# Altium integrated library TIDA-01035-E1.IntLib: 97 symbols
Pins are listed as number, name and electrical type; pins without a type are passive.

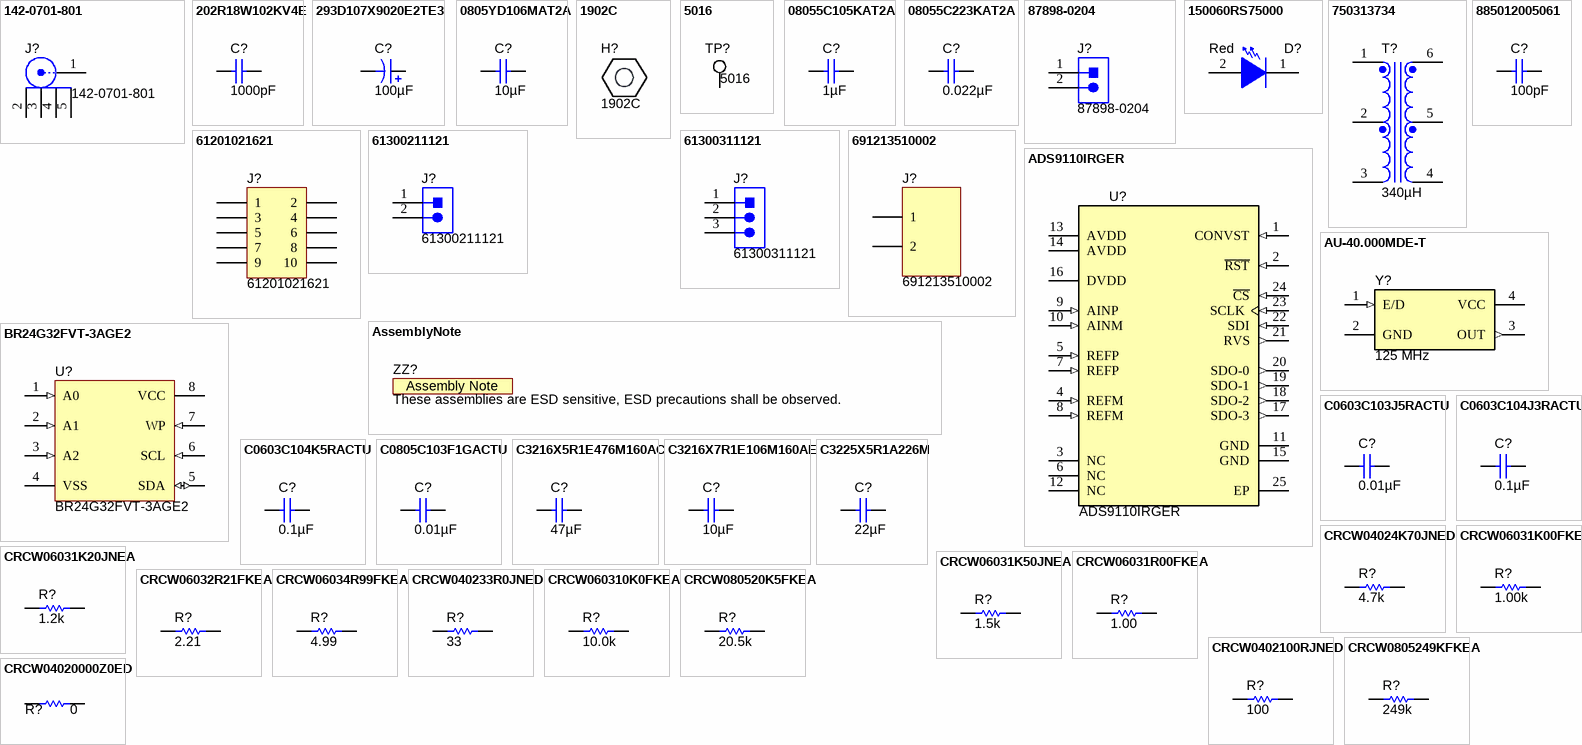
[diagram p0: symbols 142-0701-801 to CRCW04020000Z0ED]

## 142-0701-801
designator J?
Connector, End launch SMA, 50 ohm, SMT; Manufacturer: Johnson; SymbolCreator: X0208326; U/M: EA
footprint JOHNSON_142-0701-801
footprint JOHNSON_142-0701-801_NoVias
pins: 1, 2, 3, 4, 5

## 202R18W102KV4E
designator C?  ValueDisplayed: 1000pF  (hidden comment: 202R18W102KV4E)
CAP, CERM, 1000 pF, 2000 V, +/- 10%, X7R, 1206_190; Manufacturer: Johanson Technology; Polarized: N; CompType: Capacitor; Value: 1000pF; U/M: EA; Cap_F: 0.000000001; Tolerance_%: 10; Value1: Unknown; VDC_V: 2000; Value2: 2000V; TaMin_C: -55; TaMax_C: 125; Cap_Case: 1206; AEC Category: Q200
signal-integrity model Cap
simulation model Cap
footprint 1206_190
footprint 1206_190M
footprint 1206_190L
pins: 1, 2

## 293D107X9020E2TE3
designator C?  ValueDisplayed: 100µF  (hidden comment: 293D107X9020E2TE3)
CAP, TA, 100 µF, 20 V, +/- 10%, 0.5 ohm, SMD; Manufacturer: Vishay-Sprague; Polarized: Y; CompType: Capacitor; Value: 100uF; U/M: EA; Cap_F: 0.0001; Tolerance_%: 10; Value1: 0.5 ohm; VDC_V: 20; Value2: 20V; ESR_ohm: 0.5; IRMS_A: 0.57; TaMin_C: -55; TaMax_C: 125; Cap_Case: E; AEC Category: Q200
signal-integrity model Cap
simulation model Cap
footprint 7343-43
pins: 1 +, 2 -

## 0805YD106MAT2A
designator C?  ValueDisplayed: 10µF  (hidden comment: 0805YD106MAT2A)
CAP, CERM, 10uF, 16V, +/-20%, X5R, 0805; Manufacturer: AVX; Polarized: N; CompType: Capacitor; U/M: EA; Cap_F: 0.00001; Tolerance_%: 20; Value1: Unknown; VDC_V: 16; TaMin_C: -55; TaMax_C: 85; Cap_Case: 0805
signal-integrity model Cap
simulation model Cap
footprint 0805_HV
footprint 0805
footprint 0805M
footprint 0805L
pins: 1, 2

## 1902C
designator H?
Standoff, Hex, 0.5"L #4-40 Nylon; Manufacturer: Keystone; CompType: Hardware
footprint Keystone_1902C

## 5016
designator TP?
Test Point, Compact, SMT; Manufacturer: Keystone; CompType: Test Point Loop; U/M: EA
footprint Testpoint_Keystone_Compact
pins: 1

## 08055C105KAT2A
designator C?  ValueDisplayed: 1µF  (hidden comment: 08055C105KAT2A)
CAP, CERM, 1uF, 50V, +/-10%, X7R, 0805; Manufacturer: AVX; Polarized: N; CompType: Capacitor; U/M: EA; Cap_F: 0.000001; Tolerance_%: 10; Value1: Unknown; VDC_V: 50; TaMin_C: -55; TaMax_C: 125; Cap_Case: 0805
signal-integrity model Cap
simulation model Cap
footprint 0805_HV
footprint 0805
footprint 0805M
footprint 0805L
pins: 1, 2

## 08055C223KAT2A
designator C?  ValueDisplayed: 0.022µF  (hidden comment: 08055C223KAT2A)
CAP, CERM, 0.022uF, 50V, +/-10%, X7R, 0805; Manufacturer: AVX; Polarized: N; CompType: Capacitor; U/M: EA; Cap_F: 0.000000022; Tolerance_%: 10; ESR_Ohm: 0.052; Value1: 0.052 ohm; VDC_V: 50; TaMin_C: -55; TaMax_C: 125; Cap_Case: 0805
signal-integrity model Cap
simulation model Cap
footprint 0805_HV
footprint 0805
footprint 0805M
footprint 0805L
pins: 1, 2

## 87898-0204
designator J?
Header, 2.54 mm, 2x1, Gold, R/A, SMT; Manufacturer: Molex; SymbolCreator: a0412235; U/M: EA
footprint Molex_87898-0204
pins: 1, 2
1 alternate drawing of the same symbol

## 150060RS75000
designator D?  value Red  (hidden comment: 150060RS75000)
LED, Red, SMD; Manufacturer: Wurth Elektronik; Type: AlInGaP; Vf_V: 2; Value2: 2V; Io_A: 0.03; Vr_V: 5; Tjmax_C: 85; Power_TotalModule: 0.072; Value1: 0.072W; Angle: 140; U/M: EA
signal-integrity model Diode
footprint WL-SMCW_RED
pins: 1 K, 2 A

## 750313734
designator T?  ValueDisplayed: 340µH  (hidden comment: 750313734)
Transformer, 340 uH, TH; Manufacturer: Wurth Elektronik; SymbolCreator: Altium; Value: 340uH; Lp: 340; DCR_ohm: 0.419
footprint Wurth_750313638
pins: 1, 2, 3, 4, 5, 6

## 61201021621
designator J?
WR-BHD 2.54mm Male Box Header; Manufacturer: Wurth Elektronik; ComponentLink1 Description: Manufacturer; ComponentLink2 Description: Datasheet; NoPins: 10
footprint 61201021621 (10 pins, straight, gold plating)
pins: 1, 2, 3, 4, 5, 6, 7, 8, 9, 10

## 61300211121
designator J?
Header, 2.54 mm, 2x1, Gold, TH; Manufacturer: Wurth Elektronik eiSos; SymbolCreator: a0412235; U/M: EA
footprint WURTH_61300211121
pins: 1, 2
1 alternate drawing of the same symbol

## 61300311121
designator J?
Header, 2.54 mm, 3x1, Gold, TH; Manufacturer: Wurth Elektronik eiSos; SymbolCreator: a0799628; U/M: EA
footprint WURTH_61300311121
pins: 1, 2, 3
2 alternate drawings of the same symbol

## 691213510002
designator J?
Horizontal Cable Entry with Rising Cage Clamp, Serie 2135 - 5.08 mm; Manufacturer: Wurth Elektronik; ComponentLink1 Description: Manufacturer; ComponentLink2 Description: Datasheet; NoPins: 2
footprint 691213510002 (Serie 2135 - 5.08 mm _ 2 pins)
pins: 1, 2

## 885012005061
designator C?  ValueDisplayed: 100pF  (hidden comment: 885012005061)
CAP, CERM, 100 pF, 50 V, +/- 5%, C0G/NP0, 0402; Manufacturer: Wurth Elektronik; Polarized: N; CompType: Capacitor; Value: 100pF; U/M: EA; Cap_F: 0.0000000001; Tolerance_%: 5; Value1: Unknown; VDC_V: 50; Value2: 50V; TaMin_C: -55; TaMax_C: 125; Cap_Case: 0402; AEC Category: Q200
signal-integrity model Cap
simulation model Cap
footprint 0402
footprint 0402M
footprint 0402L
footprint 0402S
pins: 1, 2

## ADS9110IRGER
designator U?
18-Bit, 2-MSPS, 20-mW, SAR ADC with Enhanced Serial Interface, RGE0024H; Alternate PartNumber: ADS9110IRGET; Manufacturer: Texas Instruments; SymbolCreator: Altium; CompType: IC; U/M: EA
footprint RGE0024H
footprint RGE0024H_NV
pins: 1 CONVST (in), 2 ~{RST} (in), 3 NC, 4 REFM (in), 5 REFP (in), 6 NC, 7 REFP (in), 8 REFM (in), 9 AINP (in), 10 AINM (in), 11 GND (power), 12 NC (power), 13 AVDD (power), 14 AVDD (power), 15 GND (power), 16 DVDD (power), 17 SDO-3 (out), 18 SDO-2 (out), 19 SDO-1 (out), 20 SDO-0 (out), 21 RVS (out), 22 SDI (in), 23 SCLK (in), 24 ~{CS} (in), 25 EP (power)

## AssemblyNote
designator ZZ?, comment These assemblies are ESD sensitive, ESD precautions shall be observed.  (no BOM)
SymbolCreator: codlsc; CompType: AssemblyNote
footprint AssemblyNote

## AU-40.000MDE-T
designator Y?, comment Frequency: 125 MHz  (hidden comment: ASTMLPE-125.000MHZ-LJ-E-T)
OSC, 125 MHz, 3.3V, SMD; Manufacturer: ABRACON; SymbolCreator: a0411947; CompType: Oscillator; U/M: EA; TaMin_C: -40; TaMax_C: 85; Frequency Stability: ±50ppm
footprint TXC_AU
pins: 1 E/D (in), 2 GND (power), 3 OUT (out), 4 VCC (power)

## BR24G32FVT-3AGE2
designator U?
I2C BUS EEPROM (2-Wire), TSSOP-B8; Manufacturer: Rohm; SymbolCreator: a0411947
footprint TSOP65P640X120-8N
footprint TSOP65P640X120-8M
footprint TSOP65P640X120-8L
pins: 1 A0 (in), 2 A1 (in), 3 A2 (in), 4 VSS (power), 5 SDA (io), 6 SCL (in), 7 WP (in), 8 VCC (power)

## C0603C103J5RACTU
designator C?  ValueDisplayed: 0.01µF  (hidden comment: C0603C103J5RACTU)
CAP, CERM, 0.01uF, 50V, +/-5%, X7R, 0603; Manufacturer: Kemet; Polarized: N; CompType: Capacitor; U/M: EA; Cap_F: 0.00000001; Tolerance_%: 5; Value1: Unknown; VDC_V: 50; TaMin_C: -55; TaMax_C: 125; Cap_Case: 0603
signal-integrity model Cap
simulation model Cap
footprint 0603
footprint 0603M
footprint 0603L
footprint 0603_HV
pins: 1, 2

## C0603C104J3RACTU
designator C?  ValueDisplayed: 0.1µF  (hidden comment: C0603C104J3RACTU)
CAP, CERM, 0.1 µF, 25 V, +/- 5%, X7R, 0603; Manufacturer: Kemet; Polarized: N; CompType: Capacitor; Value: 0.1uF; U/M: EA; Cap_F: 0.0000001; Tolerance_%: 5; Value1: Unknown; VDC_V: 25; Value2: 25V; TaMin_C: -55; TaMax_C: 125; Cap_Case: 0603
signal-integrity model Cap
simulation model Cap
footprint 0603
footprint 0603M
footprint 0603L
footprint 0603_HV
footprint 0603S
pins: 1, 2

## C0603C104K5RACTU
designator C?  ValueDisplayed: 0.1µF  (hidden comment: C0603C104K5RACTU)
CAP, CERM, 0.1uF, 50V, +/-10%, X7R, 0603; Manufacturer: Kemet; Polarized: N; CompType: Capacitor; U/M: EA; Cap_F: 0.0000001; Tolerance_%: 10; Value1: Unknown; VDC_V: 50; TaMin_C: -55; TaMax_C: 125; Cap_Case: 0603
signal-integrity model Cap
simulation model Cap
footprint 0603
footprint 0603M
footprint 0603L
footprint 0603_HV
pins: 1, 2

## C0805C103F1GACTU
designator C?  ValueDisplayed: 0.01µF  (hidden comment: C0805C103F1GACTU)
CAP, CERM, 0.01 µF, 100 V, +/- 1%, C0G/NP0, 0805; Manufacturer: Kemet; Polarized: N; CompType: Capacitor; Value: 0.01uF; U/M: EA; Cap_F: 0.00000001; Tolerance_%: 1; Value1: Unknown; VDC_V: 100; Value2: 100V; TaMin_C: -55; TaMax_C: 125; Cap_Case: 0805; AEC Category: Q200
signal-integrity model Cap
simulation model Cap
footprint 0805_HV
footprint 0805_HV1
footprint 0805
footprint 0805M
footprint 0805L
pins: 1, 2

## C3216X5R1E476M160AC
designator C?  ValueDisplayed: 47µF  (hidden comment: C3216X5R1E476M160AC)
CAP, CERM, 47 µF, 25 V, +/- 20%, X5R, 1206_190; Manufacturer: TDK; Polarized: N; CompType: Capacitor; Value: 47uF; U/M: EA; Cap_F: 0.000047; Tolerance_%: 20; Value1: Unknown; VDC_V: 25; Value2: 25V; TaMin_C: -55; TaMax_C: 85; Cap_Case: 1206; AEC Category: Q200
signal-integrity model Cap
simulation model Cap
footprint 1206_190
footprint 1206_190M
footprint 1206_190L
pins: 1, 2

## C3216X7R1E106M160AE
designator C?  ValueDisplayed: 10µF  (hidden comment: C3216X7R1E106M160AE)
CAP, CERM, 10 µF, 25 V, +/- 20%, X7R, 1206_190; Manufacturer: TDK; Polarized: N; CompType: Capacitor; Value: 10uF; U/M: EA; Cap_F: 0.00001; Tolerance_%: 20; Value1: Unknown; VDC_V: 25; Value2: 25V; TaMin_C: -55; TaMax_C: 125; Cap_Case: 1206; AEC Category: Q200
signal-integrity model Cap
simulation model Cap
footprint 1206_190
footprint 1206_190M
footprint 1206_190L
pins: 1, 2

## C3225X5R1A226M
designator C?  ValueDisplayed: 22µF  (hidden comment: C3225X5R1A226M)
CAP, CERM, 22uF, 10V, +/-20%, X5R, 1210; Manufacturer: TDK; Polarized: N; CompType: Capacitor; U/M: EA; Cap_F: 0.000022; Tolerance_%: 20; ESR_Ohm: 0.002; Value1: 0.002 ohm; VDC_V: 10; IRMS_A: 3.2; TaMin_C: -55; TaMax_C: 85; Cap_Case: 1210
signal-integrity model Cap
simulation model Cap
footprint 1210 (1210 from SM-752 data)
footprint 1210M
footprint 1210L
pins: 1, 2

## CRCW04024K70JNED
designator R?  ValueDisplayed: 4.7k  (hidden comment: CRCW04024K70JNED)
RES, 4.7 k, 5%, 0.063 W, 0402; Manufacturer: Vishay-Dale; CompType: Resistor; Value: 4.7k; Res_ohm: 4700; Value_Code: 4k70; Tolerance_%: 5; Power_W: 0.063; Value2: 0.063W; VDC_V: 50; TempCo: 200 ppm/C; EIA_Code: E24; U/M: EA; AEC Category: Q200
signal-integrity model Resistor
simulation model Resistor
footprint 0402
footprint 0402M
footprint 0402L
footprint 0402S
pins: 1, 2

## CRCW06031K00FKEA
designator R?  ValueDisplayed: 1.00k  (hidden comment: CRCW06031K00FKEA)
RES, 1.00 k, 1%, 0.1 W, 0603; Manufacturer: Vishay-Dale; CompType: Resistor; Value: 1.00k; Res_ohm: 1000; Value_Code: 1k00; Tolerance_%: 1; Power_W: 0.1; Value2: 0.1W; VDC_V: 75; TempCo: 100 ppm/C; EIA_Code: E96; U/M: EA; AEC Category: Q200
signal-integrity model Resistor
simulation model Resistor
footprint 0603
footprint 0603M
footprint 0603L
footprint 0603_HV
footprint 0603S
pins: 1, 2

## CRCW06031K20JNEA
designator R?  ValueDisplayed: 1.2k  (hidden comment: CRCW06031K20JNEA)
RES, 1.2 k, 5%, 0.1 W, 0603; Manufacturer: Vishay-Dale; CompType: Resistor; Value: 1.2k; Res_ohm: 1200; Value_Code: 1k20; Tolerance_%: 5; Power_W: 0.1; Value2: 0.1W; VDC_V: 75; TempCo: 200 ppm/C; EIA_Code: E24; U/M: EA; AEC Category: Q200
signal-integrity model Resistor
simulation model Resistor
footprint 0603
footprint 0603M
footprint 0603L
footprint 0603_HV
footprint 0603S
pins: 1, 2

## CRCW06031K50JNEA
designator R?  ValueDisplayed: 1.5k  (hidden comment: CRCW06031K50JNEA)
RES, 1.5 k, 5%, 0.1 W, 0603; Manufacturer: Vishay-Dale; CompType: Resistor; Value: 1.5k; Res_ohm: 1500; Value_Code: 1k50; Tolerance_%: 5; Power_W: 0.1; Value2: 0.1W; VDC_V: 75; TempCo: 200 ppm/C; EIA_Code: E24; U/M: EA; AEC Category: Q200
signal-integrity model Resistor
simulation model Resistor
footprint 0603
footprint 0603M
footprint 0603L
footprint 0603_HV
footprint 0603S
pins: 1, 2

## CRCW06031R00FKEA
designator R?  ValueDisplayed: 1.00  (hidden comment: CRCW06031R00FKEA)
RES, 1.00, 1%, 0.1 W, 0603; Manufacturer: Vishay-Dale; CompType: Resistor; Value: 1.00; Res_ohm: 1; Value_Code: 1R00; Power_W: 0.1; Value2: 0.1W; VDC_V: 75; TempCo: 100 ppm/C; EIA_Code: E96; U/M: EA; AEC Category: Q200
signal-integrity model Resistor
simulation model Resistor
footprint 0603
footprint 0603M
footprint 0603L
footprint 0603_HV
footprint 0603S
pins: 1, 2

## CRCW06032R21FKEA
designator R?  ValueDisplayed: 2.21  (hidden comment: CRCW06032R21FKEA)
RES, 2.21, 1%, 0.1 W, 0603; Manufacturer: Vishay-Dale; CompType: Resistor; Value: 2.21; Value_Code: 2R21; Tolerance_%: 1; Power_W: 0.1; Value2: 0.1W; VDC_V: 75; TempCo: 100 ppm/C; EIA_Code: E96; U/M: EA
signal-integrity model Resistor
simulation model Resistor
footprint 0603
footprint 0603M
footprint 0603L
footprint 0603_HV
footprint 0603S
pins: 1, 2

## CRCW06034R99FKEA
designator R?  ValueDisplayed: 4.99  (hidden comment: CRCW06034R99FKEA)
RES, 4.99, 1%, 0.1 W, 0603; Manufacturer: Vishay-Dale; CompType: Resistor; Value: 4.99; Value_Code: 4R99; Tolerance_%: 1; Power_W: 0.1; Value2: 0.1W; VDC_V: 75; TempCo: 100 ppm/C; EIA_Code: E96; U/M: EA; AEC Category: Q200
signal-integrity model Resistor
simulation model Resistor
footprint 0603
footprint 0603M
footprint 0603L
footprint 0603_HV
footprint 0603S
pins: 1, 2

## CRCW040233R0JNED
designator R?  ValueDisplayed: 33  (hidden comment: CRCW040233R0JNED)
RES, 33, 5%, 0.063 W, 0402; Manufacturer: Vishay-Dale; CompType: Resistor; Value: 33; Value_Code: 33R0; Tolerance_%: 5; Power_W: 0.063; Value2: 0.063W; VDC_V: 50; TempCo: 200 ppm/C; EIA_Code: E24; U/M: EA; AEC Category: Q200
signal-integrity model Resistor
simulation model Resistor
footprint 0402
footprint 0402M
footprint 0402L
footprint 0402S
pins: 1, 2

## CRCW060310K0FKEA
designator R?  ValueDisplayed: 10.0k  (hidden comment: CRCW060310K0FKEA)
RES, 10.0 k, 1%, 0.1 W, 0603; Manufacturer: Vishay-Dale; CompType: Resistor; Value: 10.0k; Res_ohm: 10000; Value_Code: 10k0; Tolerance_%: 1; Power_W: 0.1; Value2: 0.1W; VDC_V: 75; TempCo: 100 ppm/C; EIA_Code: E96; U/M: EA
signal-integrity model Resistor
simulation model Resistor
footprint 0603
footprint 0603M
footprint 0603L
footprint 0603_HV
footprint 0603S
pins: 1, 2

## CRCW080520K5FKEA
designator R?  ValueDisplayed: 20.5k  (hidden comment: CRCW080520K5FKEA)
RES, 20.5 k, 1%, 0.125 W, 0805; Manufacturer: Vishay-Dale; CompType: Resistor; Value: 20.5k; Res_ohm: 20500; Value_Code: 20k5; Tolerance_%: 1; Power_W: 0.125; Value2: 0.125W; VDC_V: 150; TempCo: 100 ppm/C; EIA_Code: E96; U/M: EA; AEC Category: Q200
signal-integrity model Resistor
simulation model Resistor
footprint 0805_HV
footprint 0805_HV1
footprint 0805
footprint 0805M
pins: 1, 2

## CRCW0402100RJNED
designator R?  ValueDisplayed: 100  (hidden comment: CRCW0402100RJNED)
RES, 100, 5%, 0.063 W, 0402; Manufacturer: Vishay-Dale; CompType: Resistor; Value: 100; Value_Code: 100R; Tolerance_%: 5; Power_W: 0.063; Value2: 0.063W; VDC_V: 50; TempCo: 200 ppm/C; EIA_Code: E24; U/M: EA; AEC Category: Q200
signal-integrity model Resistor
simulation model Resistor
footprint 0402
footprint 0402M
footprint 0402L
footprint 0402S
pins: 1, 2

## CRCW0805249KFKEA
designator R?  value 249k  (hidden comment: CRCW0805249KFKEA)
RES, 249k ohm, 1%, 0.125W, 0805; Manufacturer: Vishay-Dale; CompType: Resistor; Res_ohm: 249000; Tolerance_%: 1; Power_W: 0.125; VDC_V: 150; TempCo: 100 ppm/C; EIA_Code: E96; U/M: EA
signal-integrity model Resistor
simulation model Resistor
footprint 0805_HV
footprint 0805
footprint 0805M
footprint 0805L
pins: 1, 2

## CRCW04020000Z0ED
designator R?  ValueDisplayed: 0  (hidden comment: CRCW04020000Z0ED)
RES, 0, 5%, 0.063 W, 0402; Manufacturer: Vishay-Dale; CompType: Resistor; Value: 0; Value_Code: 0000; Tolerance_%: 5; Power_W: 0.063; Value2: 0.063W; VDC_V: 50; TempCo: 200 ppm/C; EIA_Code: E24; U/M: EA; AEC Category: Q200
signal-integrity model Resistor
simulation model Resistor
footprint 0402
footprint 0402M
footprint 0402L
footprint 0402S
pins: 1, 2

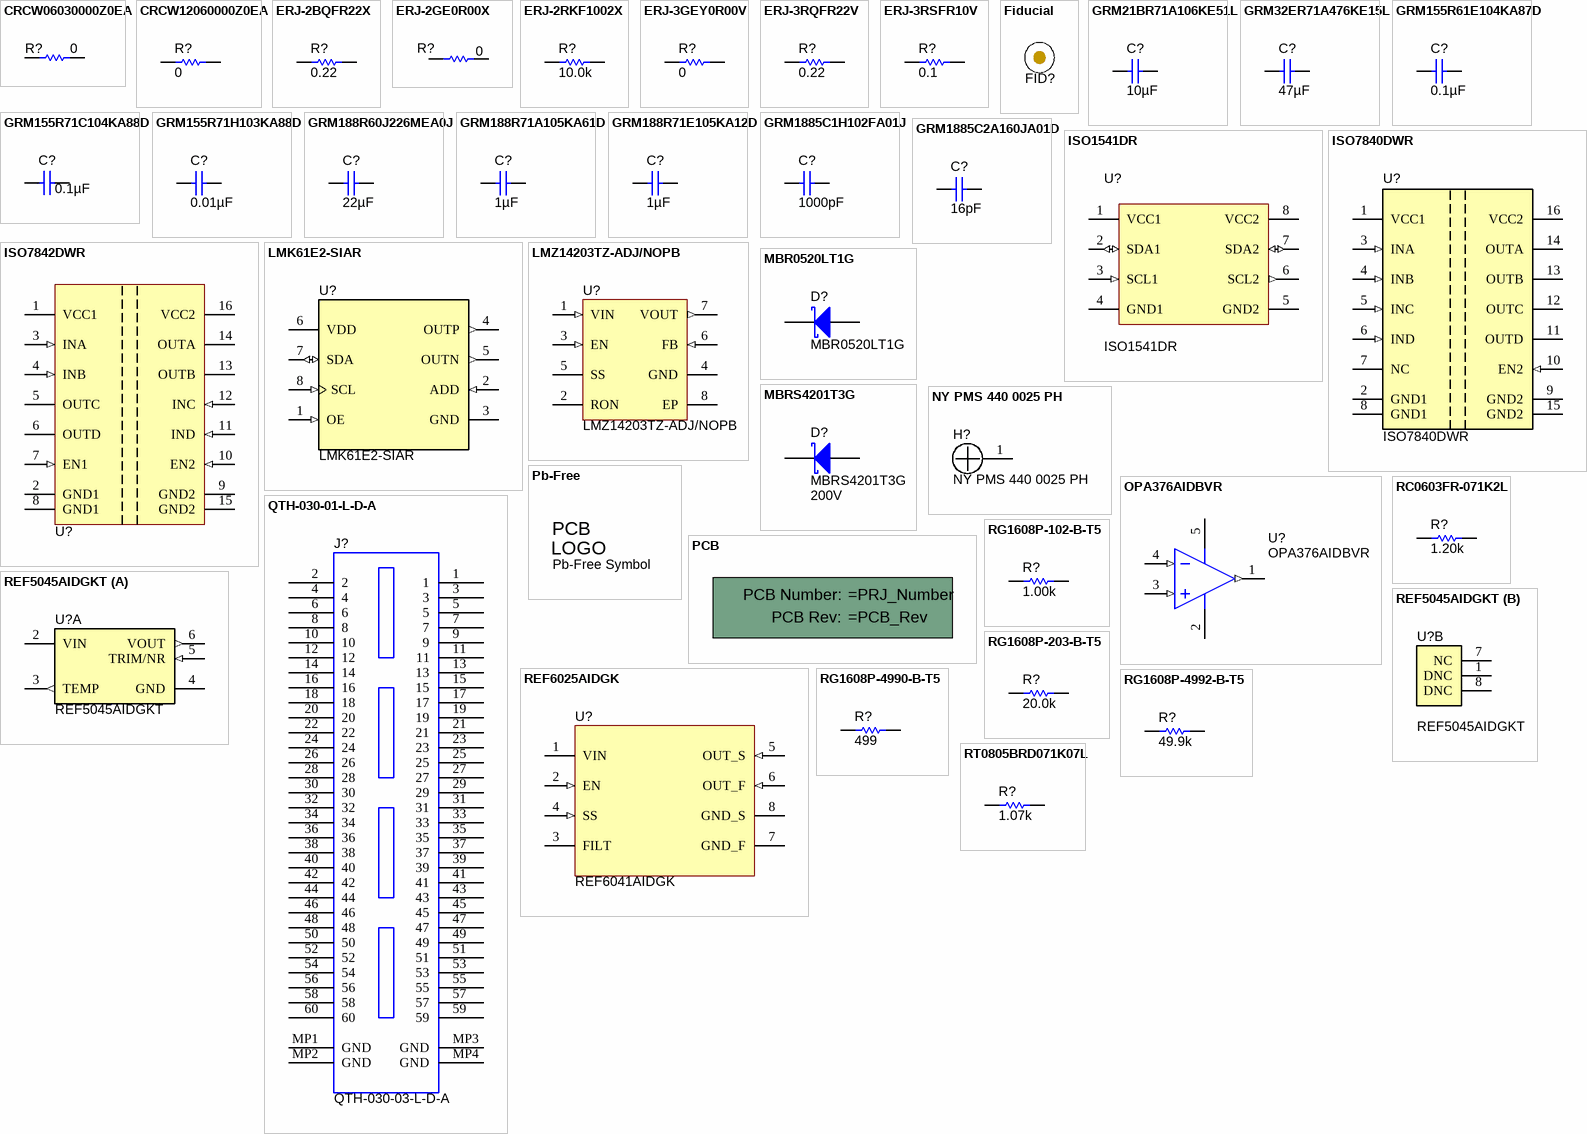
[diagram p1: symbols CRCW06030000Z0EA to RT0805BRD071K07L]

## CRCW06030000Z0EA
designator R?  ValueDisplayed: 0  (hidden comment: CRCW06030000Z0EA)
RES, 0, 5%, 0.1 W, 0603; Manufacturer: Vishay-Dale; CompType: Resistor; Value: 0; Value_Code: 0000; Tolerance_%: 5; Power_W: 0.1; Value2: 0.1W; VDC_V: 75; TempCo: 200 ppm/C; EIA_Code: E24; U/M: EA; AEC Category: Q200
signal-integrity model Resistor
simulation model Resistor
footprint 0603
footprint 0603M
footprint 0603L
footprint 0603_HV
footprint 0603S
pins: 1, 2

## CRCW12060000Z0EA
designator R?  ValueDisplayed: 0  (hidden comment: CRCW12060000Z0EA)
RES, 0, 5%, 0.25 W, 1206; Manufacturer: Vishay-Dale; CompType: Resistor; Value: 0; Value_Code: 0000; Tolerance_%: 5; Power_W: 0.25; Value2: 0.25W; VDC_V: 200; TempCo: 200 ppm/C; EIA_Code: E24; U/M: EA; AEC Category: Q200
signal-integrity model Resistor
simulation model Resistor
footprint 1206
footprint 1206M
footprint 1206L
pins: 1, 2

## ERJ-2BQFR22X
designator R?  ValueDisplayed: 0.22  (hidden comment: ERJ-2BQFR22X)
RES, 0.22, 1%, 0.125 W, 0402; Manufacturer: Panasonic; CompType: Resistor; Value: 0.22; Value_Code: R220; Tolerance_%: 1; Power_W: 0.125; Value2: 0.125W; TempCo: 250 ppm/C; EIA_Code: E96; U/M: EA; AEC Category: Q200
signal-integrity model Resistor
simulation model Resistor
footprint 0402
footprint 0402M
footprint 0402L
footprint 0402S
pins: 1, 2

## ERJ-2GE0R00X
designator R?  ValueDisplayed: 0  (hidden comment: ERJ-2GE0R00X)
RES, 0, 5%, 0.063 W, 0402; Manufacturer: Panasonic; CompType: Resistor; Value: 0; Value_Code: 0000; Tolerance_%: 5; Power_W: 0.063; Value2: 0.063W; VDC_V: 50; TempCo: 600 ppm/C; EIA_Code: E24; U/M: EA; AEC Category: Q200
signal-integrity model Resistor
simulation model Resistor
footprint 0402
footprint 0402M
footprint 0402L
footprint 0402S
pins: 1, 2

## ERJ-2RKF1002X
designator R?  ValueDisplayed: 10.0k  (hidden comment: ERJ-2RKF1002X)
RES, 10.0 k, 1%, 0.1 W, 0402; Manufacturer: Panasonic; CompType: Resistor; Value: 10.0k; Res_ohm: 10000; Value_Code: 10k0; Tolerance_%: 1; Power_W: 0.1; Value2: 0.1W; VDC_V: 50; TempCo: 100 ppm/C; EIA_Code: E96; U/M: EA; AEC Category: Q200
signal-integrity model Resistor
simulation model Resistor
footprint 0402
footprint 0402M
footprint 0402L
footprint 0402S
pins: 1, 2

## ERJ-3GEY0R00V
designator R?  ValueDisplayed: 0  (hidden comment: ERJ-3GEY0R00V)
RES, 0, 5%, 0.1 W, 0603; Manufacturer: Panasonic; CompType: Resistor; Value: 0; Value_Code: 0000; Tolerance_%: 5; Power_W: 0.1; Value2: 0.1W; VDC_V: 50; TempCo: 600 ppm/C; EIA_Code: E24; U/M: EA; AEC Category: Q200
signal-integrity model Resistor
simulation model Resistor
footprint 0603
footprint 0603M
footprint 0603L
footprint 0603_HV
footprint 0603S
pins: 1, 2

## ERJ-3RQFR22V
designator R?  value 0.22  (hidden comment: ERJ-3RQFR22V)
RES, 0.22 ohm, 1%, 0.1W, 0603; Manufacturer: Panasonic; CompType: Resistor; Value_Code: R220; Tolerance_%: 1; Power_W: 0.1; TempCo: 300 ppm/C; EIA_Code: E96; U/M: EA
signal-integrity model Resistor
simulation model Resistor
footprint 0603
footprint 0603M
footprint 0603L
footprint 0603_HV
pins: 1, 2

## ERJ-3RSFR10V
designator R?  ValueDisplayed: 0.1  (hidden comment: ERJ-3RSFR10V)
RES, 0.1, 1%, 0.1 W, 0603; Manufacturer: Panasonic; CompType: Resistor; Value: 0.1; Value_Code: R100; Tolerance_%: 1; Value2: 0.1W; TempCo: 300 ppm/C; EIA_Code: E96; U/M: EA; AEC Category: Q200
signal-integrity model Resistor
simulation model Resistor
footprint 0603
footprint 0603M
footprint 0603L
footprint 0603_HV
footprint 0603S
pins: 1, 2

## Fiducial
designator FID?  (value not drawn)
Fiducial mark.  There is nothing to buy or mount.; SymbolCreator: codlsc
footprint Fiducial10-30
footprint Fiducial10-20
footprint Fiducial15-30
footprint Fiducial20-40
footprint Fiducial6.4-20

## GRM21BR71A106KE51L
designator C?  ValueDisplayed: 10µF  (hidden comment: GRM21BR71A106KE51L)
CAP, CERM, 10 µF, 10 V, +/- 10%, X7R, 0805; Manufacturer: MuRata; Polarized: N; CompType: Capacitor; Value: 10uF; U/M: EA; Cap_F: 0.00001; Tolerance_%: 10; ESR_ohm: 0.003; Value1: 0.003 ohm; Value2: 10V; TaMin_C: -55; TaMax_C: 125; Cap_Case: 0805; AEC Category: Q200
signal-integrity model Cap
simulation model Cap
footprint 0805_HV
footprint 0805_HV1
footprint 0805
footprint 0805M
footprint 0805L
pins: 1, 2

## GRM32ER71A476KE15L
designator C?  ValueDisplayed: 47µF  (hidden comment: GRM32ER71A476KE15L)
CAP, CERM, 47 µF, 10 V, +/- 10%, X7R, 1210; Manufacturer: MuRata; Polarized: N; CompType: Capacitor; Value: 47uF; U/M: EA; Cap_F: 0.000047; Tolerance_%: 10; Value1: Unknown; Value2: 10V; TaMin_C: -55; TaMax_C: 125; Cap_Case: 1210
signal-integrity model Cap
simulation model Cap
footprint 1210 (1210 from SM-752 data)
footprint 1210M
footprint 1210L
pins: 1, 2

## GRM155R61E104KA87D
designator C?  ValueDisplayed: 0.1µF  (hidden comment: GRM155R61E104KA87D)
CAP, CERM, 0.1 µF, 25 V, +/- 10%, X5R, 0402; Manufacturer: MuRata; Polarized: N; CompType: Capacitor; Value: 0.1uF; U/M: EA; Cap_F: 0.0000001; Tolerance_%: 10; Value1: Unknown; VDC_V: 25; Value2: 25V; TaMin_C: -55; TaMax_C: 85; Cap_Case: 0402; AEC Category: Q200
signal-integrity model Cap
simulation model Cap
footprint 0402
footprint 0402M
footprint 0402L
footprint 0402S
pins: 1, 2

## GRM155R71C104KA88D
designator C?  ValueDisplayed: 0.1µF  (hidden comment: GRM155R71C104KA88D)
CAP, CERM, 0.1 µF, 16 V, +/- 10%, X7R, 0402; Manufacturer: MuRata; Polarized: N; CompType: Capacitor; Value: 0.1uF; U/M: EA; Cap_F: 0.0000001; Tolerance_%: 10; Value1: Unknown; VDC_V: 16; Value2: 16V; TaMin_C: -55; TaMax_C: 125; Cap_Case: 0402
signal-integrity model Cap
simulation model Cap
footprint 0402
footprint 0402M
footprint 0402L
footprint 0402S
pins: 1, 2

## GRM155R71H103KA88D
designator C?  ValueDisplayed: 0.01µF  (hidden comment: GRM155R71H103KA88D)
CAP, CERM, 0.01 µF, 50 V, +/- 10%, X7R, 0402; Manufacturer: MuRata; Polarized: N; CompType: Capacitor; Value: 0.01uF; U/M: EA; Cap_F: 0.00000001; Tolerance_%: 10; Value1: Unknown; VDC_V: 50; Value2: 50V; TaMin_C: -55; TaMax_C: 125; Cap_Case: 0402
signal-integrity model Cap
simulation model Cap
footprint 0402
footprint 0402M
footprint 0402L
footprint 0402S
pins: 1, 2

## GRM188R60J226MEA0J
designator C?  ValueDisplayed: 22µF  (hidden comment: GRM188R60J226MEA0J)
CAP, CERM, 22 µF, 6.3 V, +/- 20%, X5R, 0603; Manufacturer: MuRata; Polarized: N; CompType: Capacitor; Value: 22uF; U/M: EA; Cap_F: 0.000022; Tolerance_%: 20; Value1: Unknown; VDC_V: 6.3; Value2: 6.3V; TaMin_C: -55; TaMax_C: 85; Cap_Case: 0603; AEC Category: Q200
signal-integrity model Cap
simulation model Cap
footprint 0603
footprint 0603M
footprint 0603L
footprint 0603_HV
footprint 0603S
pins: 1, 2

## GRM188R71A105KA61D
designator C?  ValueDisplayed: 1µF  (hidden comment: GRM188R71A105KA61D)
CAP, CERM, 1uF, 10V, +/-10%, X7R, 0603; Manufacturer: MuRata; Polarized: N; CompType: Capacitor; U/M: EA; Cap_F: 0.000001; Tolerance_%: 10; ESR_Ohm: 0.011; Value1: 0.011 ohm; TaMin_C: -55; TaMax_C: 125; Cap_Case: 0603
signal-integrity model Cap
simulation model Cap
footprint 0603
footprint 0603M
footprint 0603L
footprint 0603_HV
pins: 1, 2

## GRM188R71E105KA12D
designator C?  ValueDisplayed: 1µF  (hidden comment: GRM188R71E105KA12D)
CAP, CERM, 1 µF, 25 V, +/- 10%, X7R, 0603; Manufacturer: MuRata; Polarized: N; CompType: Capacitor; Value: 1uF; U/M: EA; Cap_F: 0.000001; Tolerance_%: 10; Value1: Unknown; VDC_V: 25; Value2: 25V; TaMin_C: -55; TaMax_C: 125; Cap_Case: 0603; AEC Category: Q200
signal-integrity model Cap
simulation model Cap
footprint 0603
footprint 0603M
footprint 0603L
footprint 0603_HV
footprint 0603S
pins: 1, 2

## GRM1885C1H102FA01J
designator C?  ValueDisplayed: 1000pF  (hidden comment: GRM1885C1H102FA01J)
CAP, CERM, 1000 pF, 50 V, +/- 1%, C0G/NP0, 0603; Manufacturer: MuRata; Polarized: N; CompType: Capacitor; Value: 1000pF; U/M: EA; Cap_F: 0.000000001; Tolerance_%: 1; Value1: Unknown; VDC_V: 50; Value2: 50V; TaMin_C: -55; TaMax_C: 125; Cap_Case: 0603; AEC Category: Q200
signal-integrity model Cap
simulation model Cap
footprint 0603
footprint 0603M
footprint 0603L
footprint 0603_HV
footprint 0603S
pins: 1, 2

## GRM1885C2A160JA01D
designator C?  ValueDisplayed: 16pF  (hidden comment: GRM1885C2A160JA01D)
CAP, CERM, 16 pF, 100 V, +/- 5%, C0G/NP0, 0603; Manufacturer: MuRata; Polarized: N; CompType: Capacitor; Value: 16pF; U/M: EA; Cap_F: 0.000000000016; Tolerance_%: 5; Value1: Unknown; VDC_V: 100; Value2: 100V; TaMin_C: -55; TaMax_C: 125; Cap_Case: 0603; AEC Category: Q200
signal-integrity model Cap
simulation model Cap
footprint 0603
footprint 0603M
footprint 0603L
footprint 0603_HV
footprint 0603S
pins: 1, 2

## ISO1541DR
designator U?
Low-Power Bidirectional I2C Isolators, D0008A; Manufacturer: Texas Instruments; SymbolCreator: a0411947; CompType: IC; U/M: EA
footprint D0008A_N
footprint D0008A_M
footprint D0008A_L
pins: 1 VCC1 (power), 2 SDA1 (io), 3 SCL1 (in), 4 GND1 (power), 5 GND2 (power), 6 SCL2 (out), 7 SDA2 (io), 8 VCC2 (power)
1 alternate drawing of the same symbol

## ISO7840DWR
designator U?
High-Performance, 8000 VPK Reinforced Quad-Channel Digital Isolator, DW0016B; Manufacturer: Texas Instruments; SymbolCreator: a0411947; CompType: IC; U/M: EA
footprint DW0016B_N
footprint DW0016B_M
footprint DW0016B_L
footprint DW0016B_HV
pins: 1 VCC1 (power) "Power supply, VCC1", 2 GND1 (power) "Ground connection for VCC1", 3 INA (in) "Input, channel A", 4 INB (in) "Input, channel B", 5 INC (in) "Output, channel C", 6 IND (in) "Output, channel D", 7 NC "Output enable", 8 GND1 (power) "Ground connection for VCC1", 9 GND2 (power) "Ground connection for VCC2", 10 EN2 (in) "Output enable", 11 OUTD (hiz) "Input, channel D", 12 OUTC (hiz) "Input, channel C", 13 OUTB (hiz) "Output, channel B", 14 OUTA (hiz) "Output, channel A", 15 GND2 (power) "Ground connection for VCC2", 16 VCC2 (power) "Power supply, VCC2"

## ISO7842DWR
designator U?  (value not drawn)
High-Performance, 8000 VPK Reinforced Quad Channel Digital Isolator, DW0016B; Manufacturer: Texas Instruments; SymbolCreator: Altium; CompType: IC; U/M: EA
footprint DW0016B_N
footprint DW0016B_M
footprint DW0016B_L
footprint DW0016B_HV
pins: 1 VCC1 (power) "Power supply, VCC1", 2 GND1 (power) "Ground connection for VCC1", 3 INA (in) "Input, channel A", 4 INB (in) "Input, channel B", 5 OUTC (hiz) "Output, channel C", 6 OUTD (hiz) "Output, channel D", 7 EN1 (in) "Output enable", 8 GND1 (power) "Ground connection for VCC1", 9 GND2 (power) "Ground connection for VCC2", 10 EN2 (in) "Output enable", 11 IND (in) "Input, channel D", 12 INC (in) "Input, channel C", 13 OUTB (hiz) "Output, channel B", 14 OUTA (hiz) "Output, channel A", 15 GND2 (power) "Ground connection for VCC2", 16 VCC2 (power) "Power supply, VCC2"

## LMK61E2-SIAR
designator U?
Ultra-Low Jitter Programmable Oscillator with Internal EEPROM, SIA0008B; Alternate PartNumber: LMK61E2-SIAT; Manufacturer: Texas Instruments; SymbolCreator: Altium; CompType: IC; U/M: EA
footprint SIA0008B
pins: 1 OE (in), 2 ADD (in), 3 GND (power), 4 OUTP (out), 5 OUTN (out), 6 VDD (power), 7 SDA (io), 8 SCL (in)

## LMZ14203TZ-ADJ/NOPB
designator U?
3A SIMPLE SWITCHER® Power Module with 42V Maximum Input Voltage, 7-pin TO-PMOD, Pb-Free; Manufacturer: Texas Instruments; PackageTopMarking: NSUZXYTTE#*LMZ14203*TZ-ADJ; PowerWise: Y
footprint TZA07A_V (D2-PAK, 8-Leads, Body 9.9x10.2mm, Pitch 1.27mm, Lead Span 13.8mm, NSC Recommended)
pins: 1 VIN (in), 2 RON, 3 EN (in), 4 GND (power), 5 SS, 6 FB (in), 7 VOUT (out), 8 EP

## MBR0520LT1G
designator D?
Diode, Schottky, 20 V, 0.5 A, SOD-123; Manufacturer: ON Semiconductor; U/M: EA; Vf_V: 0.385; Value: 20V; Value1: 0.5A; Value2: 0.385V; Io_A: 0.5; Vr_V: 20; TJmax_C: 125; RJC_CperW: 150; AEC Category: Q101
signal-integrity model Diode
simulation model mbr0520lt1
footprint SOD-123
pins: 1 K, 2 A

## MBRS4201T3G
designator D?  value 200V  (hidden comment: MBRS4201T3G)
Diode, Schottky, 200V, 4A, SMC; Manufacturer: ON Semiconductor; Io_A: 4
footprint SMC (Footprint not found)
pins: 1 K, 2 A

## NY PMS 440 0025 PH
designator H?
Machine Screw, Round, #4-40 x 1/4, Nylon, Philips panhead; Manufacturer: B&F Fastener Supply; CompType: Hardware; SymbolCreator: codlsc; U/M: EA
footprint NY PMS 440 0025 PH
footprint NY PMS 440 0025 PH_3Donly
pins: 1

## OPA376AIDBVR
designator U?
Precision, Low Noise, Low Iq Operational Amplifier, 2.2 to 5.5 V, -40 to 125 degC, 5-pin SOT23 (DBV0005A), Green (RoHS & no Sb/Br); Manufacturer: Texas Instruments; Alternate PartNumber: Equivalent; CMRR(Min)(dB): 76; IIB(Max)(pA): 10; Iq per channel(Max)(mA): 0.95; Number of Channels: 1; Offset Drift(Typ)(uV/C): 0.32; Slew Rate(Typ)(V/us): 2; Sub Family: Low Input Bias Current Amp (<=10pA), Low Noise Amp (<=10nV/rtHz), Low Offset Voltage Amplifier (<=500uV), Low Supply Voltage Amplifier (<=2.7V), Precision Amplifier; Total Supply Voltage(Max)(+5V is 5, +/-5V is 10): 5.5; Total Supply Voltage(Min)(+5V is 5, +/-5V is 10): 2.2; Vio (25C)(Max)(mV): 0.025; Vn at 1kHz(Typ)(nV/rtHz): 7.5
footprint DBV0005A_N (SOT23, 5-Leads, Body 2.9x1.6mm, Pitch 0.95mm, IPC Medium Density)
footprint DBV0005A_L (SOT23, 5-Leads, Body 2.9x1.6mm, Pitch 0.95mm, IPC Low Density)
footprint DBV0005A_M (SOT23, 5-Leads, Body 2.9x1.6mm, Pitch 0.95mm, IPC Low Density)
pins: 1 OUT (out), 2 V- (power), 3 IN+ (in), 4 IN- (in), 5 V+ (power)

## Pb-Free
designator Logo?, comment Pb-Free Symbol  (no BOM)
SymbolCreator: a0412235
footprint Pb-Free_Overlay_Medium
footprint Pb-Free_Overlay_Small

## PCB
designator !PCB?, comment Printed Circuit Board  (value not drawn)  (mechanical)
Manufacturer: Any; SymbolCreator: a0412235; CompType: PCB
1 alternate drawing of the same symbol

## QTH-030-01-L-D-A
designator J?, comment QTH-030-03-L-D-A
Header(Shrouded), 19.7mil, 30x2, Gold, SMT; Manufacturer: Samtec; SymbolCreator: Altium; U/M: EA
footprint Samtec_QTH-030-01-x-D-A
pins: 1, 2, 3, 4, 5, 6, 7, 8, 9, 10, 11, 12, 13, 14, 15, 16, 17, 18, 19, 20, 21, 22, 23, 24, 25, 26, 27, 28, 29, 30, 31, 32, 33, 34, 35, 36, 37, 38, 39, 40, 41, 42, 43, 44, 45, 46, 47, 48, 49, 50, 51, 52, 53, 54, 55, 56, 57, 58, 59, 60, MP1 GND, MP2 GND, MP3 GND, MP4 GND

## RC0603FR-071K2L
designator R?  ValueDisplayed: 1.20k  (hidden comment: RC0603FR-071K2L)
RES, 1.20 k, 1%, 0.1 W, 0603; Manufacturer: Yageo America; CompType: Resistor; Value: 1.20k; Res_ohm: 1200; Value_Code: 1k20; Tolerance_%: 1; Power_W: 0.1; Value2: 0.1W; VDC_V: 150; TempCo: 200 ppm/C; U/M: EA; AEC Category: Q200
signal-integrity model Resistor
simulation model Resistor
footprint 0603
footprint 0603M
footprint 0603L
footprint 0603_HV
footprint 0603S
pins: 1, 2

## REF5045AIDGKT
designator U?
Low Noise, Very Low Drift, Precision Voltage Reference, -40 to 125 degC, 8-pin MSOP (DGK), Green (RoHS & no Sb/Br); Manufacturer: Texas Instruments; Alternate PartNumber: Equivalent; Initial Accuracy @ 25/deg C(%): 0.05; Iout/Iz(Max)(mA): 10; Iq(Max)(uA): 1000; Rating: Catalog; SubFamily: Series Voltage Reference; Temp Coeff(Max)(ppm/ degree C): 3; VI(Max)(V): 18; VI(Min)(V): 4.7; VO(V): 4.5
footprint DGK0008A_N (SOP, 8-Leads, Body 3x3mm, Pitch 0.65mm, IPC Medium Density)
footprint DGK0008A_L (SOP, 8-Leads, Body 3x3mm, Pitch 0.65mm, IPC High Density)
footprint DGK0008A_M (SOP, 8-Leads, Body 3x3mm, Pitch 0.65mm, IPC Low Density)
part A pins: 2 VIN (power), 3 TEMP (out), 4 GND (power), 5 TRIM/NR (in), 6 VOUT (out)
part B pins: 1 DNC "Do not connect", 7 NC "No internal connection", 8 DNC "Do not connect"

## REF6025AIDGK
designator U?, comment REF6041AIDGK
High-Precision Voltage Reference with Integrated High-Bandwidth Buffer, DGK0008A; Manufacturer: Texas Instruments; SymbolCreator: Altium; CompType: IC; U/M: EA
footprint DGK0008A_N
footprint DGK0008A_M
footprint DGK0008A_L
pins: 1 VIN (power), 2 EN (in), 3 FILT, 4 SS (in), 5 OUT_S (in), 6 OUT_F (in), 7 GND_F (power), 8 GND_S (power)
1 alternate drawing of the same symbol

## RG1608P-102-B-T5
designator R?  ValueDisplayed: 1.00k  (hidden comment: RG1608P-102-B-T5)
RES, 1.00 k, 0.1%, 0.1 W, 0603; Manufacturer: Susumu Co Ltd; CompType: Resistor; Value: 1.00k; Res_ohm: 1000; Value_Code: 1k00; Tolerance_%: 0.1; Value2: 0.1W; VDC_V: 75; TempCo: 25 ppm/C; EIA_Code: E192; U/M: EA
signal-integrity model Resistor
simulation model Resistor
footprint 0603
footprint 0603M
footprint 0603L
footprint 0603_HV
footprint 0603S
pins: 1, 2

## RG1608P-203-B-T5
designator R?  ValueDisplayed: 20.0k  (hidden comment: RG1608P-203-B-T5)
RES, 20.0 k, 0.1%, 0.1 W, 0603; Manufacturer: Susumu Co Ltd; CompType: Resistor; Value: 20.0k; Res_ohm: 20000; Value_Code: 20k0; Tolerance_%: 0.1; Value2: 0.1W; VDC_V: 75; TempCo: 25 ppm/C; EIA_Code: E192; U/M: EA; AEC Category: Q200
signal-integrity model Resistor
simulation model Resistor
footprint 0603
footprint 0603M
footprint 0603L
footprint 0603_HV
footprint 0603S
pins: 1, 2

## RG1608P-4990-B-T5
designator R?  ValueDisplayed: 499  (hidden comment: RG1608P-4990-B-T5)
RES, 499, 0.1%, 0.1 W, 0603; Manufacturer: Susumu Co Ltd; CompType: Resistor; Value: 499; Value_Code: 499R; Tolerance_%: 0.1; Value2: 0.1W; VDC_V: 75; TempCo: 25 ppm/C; EIA_Code: E192; U/M: EA; AEC Category: Q200
signal-integrity model Resistor
simulation model Resistor
footprint 0603
footprint 0603M
footprint 0603L
footprint 0603_HV
footprint 0603S
pins: 1, 2

## RG1608P-4992-B-T5
designator R?  ValueDisplayed: 49.9k  (hidden comment: RG1608P-4992-B-T5)
RES, 49.9 k, 0.1%, 0.1 W, 0603; Manufacturer: Susumu Co Ltd; CompType: Resistor; Value: 49.9k; Res_ohm: 49900; Value_Code: 49k9; Tolerance_%: 0.1; Value2: 0.1W; VDC_V: 75; TempCo: 25 ppm/C; EIA_Code: E192; U/M: EA; AEC Category: Q200
signal-integrity model Resistor
simulation model Resistor
footprint 0603
footprint 0603M
footprint 0603L
footprint 0603_HV
footprint 0603S
pins: 1, 2

## RT0805BRD071K07L
designator R?  ValueDisplayed: 1.07k  (hidden comment: RT0805BRD071K07L)
RES, 1.07 k, 0.1%, 0.125 W, 0805; Manufacturer: Yageo America; CompType: Resistor; Value: 1.07k; Res_ohm: 1070; Value_Code: 1k07; Tolerance_%: 0.1; Power_W: 0.125; Value2: 0.125W; VDC_V: 150; TempCo: 25 ppm/C; EIA_Code: E192; U/M: EA; AEC Category: Q200
signal-integrity model Resistor
simulation model Resistor
footprint 0805_HV
footprint 0805_HV1
footprint 0805
footprint 0805M
pins: 1, 2

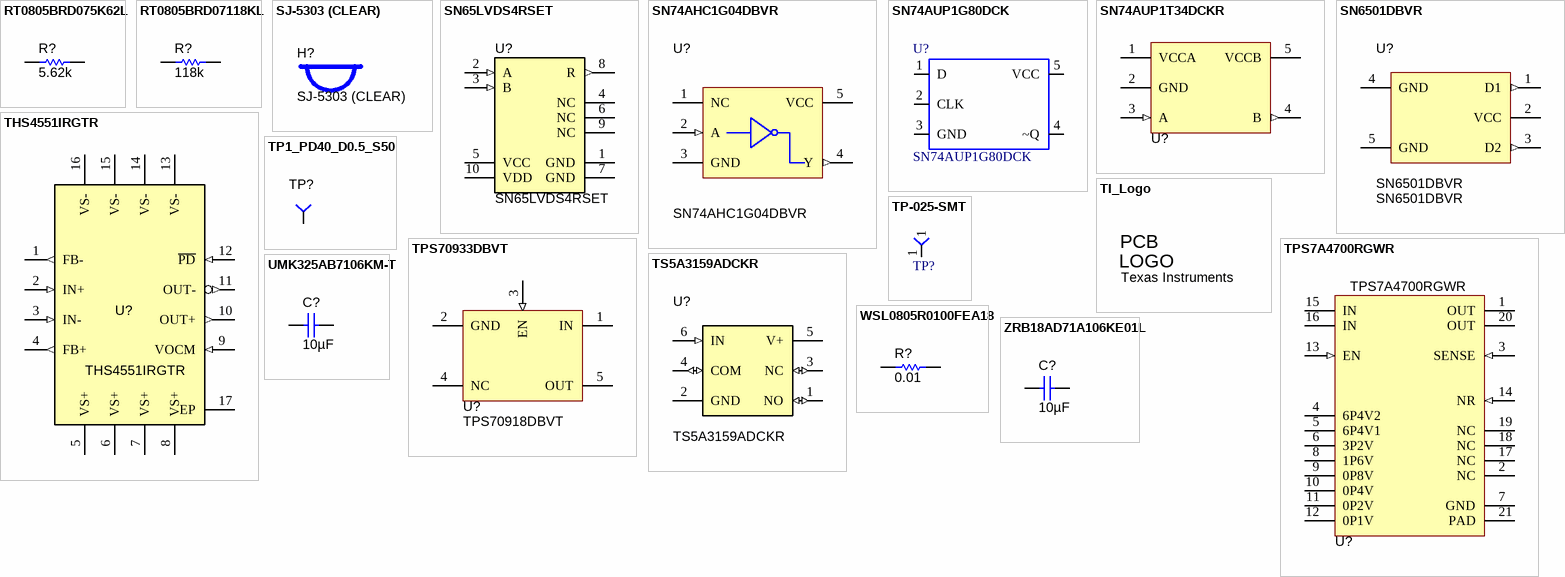
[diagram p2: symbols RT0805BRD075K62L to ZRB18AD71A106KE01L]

## RT0805BRD075K62L
designator R?  ValueDisplayed: 5.62k  (hidden comment: RT0805BRD075K62L)
RES, 5.62 k, 0.1%, 0.125 W, 0805; Manufacturer: Yageo America; CompType: Resistor; Value: 5.62k; Res_ohm: 5620; Value_Code: 5k62; Tolerance_%: 0.1; Power_W: 0.125; Value2: 0.125W; VDC_V: 150; TempCo: 25 ppm/C; EIA_Code: E192; U/M: EA; AEC Category: Q200
signal-integrity model Resistor
simulation model Resistor
footprint 0805_HV
footprint 0805_HV1
footprint 0805
footprint 0805M
pins: 1, 2

## RT0805BRD07118KL
designator R?  value 118k  (hidden comment: RT0805BRD07118KL)
RES, 118k ohm, 0.1%, 0.125W, 0805; Manufacturer: Yageo America; CompType: Resistor; Res_ohm: 118000; Tolerance_%: 0.1; Power_W: 0.125; VDC_V: 150; TempCo: 25 ppm/C; EIA_Code: E192; U/M: EA
signal-integrity model Resistor
simulation model Resistor
footprint 0805_HV
footprint 0805
footprint 0805M
footprint 0805L
pins: 1, 2

## SJ-5303 (CLEAR)
designator H?
Bumpon, Hemisphere, 0.44 X 0.20, Clear; Manufacturer: 3M; SymbolCreator: a0412235
footprint Bumpon_SJ5003Transparent

## SN65LVDS4RSET
designator U?
500 Mbps High-Speed Differential Line Driver / Receivers with LVDS Input and LVTTL / LVCMOS Output, 1 Rx, -40 to +85 degC, 10-pin UQFN (RSE), Green (RoHS & no Sb/Br); Manufacturer: Texas Instruments; Alternate PartNumber: Equivalent; ESD HBM(kV): 2; Function: Transceiver; No. of Rx: 1; No. of Tx: 0; Output Signal: LVTTL, LVCMOS; Signaling Rate(Mbps): 500; SubFamily: LVDS PHY (<800Mbps)
footprint RSE0010A (QFN, 10-Leads, Body 1.5x2mm, Pitch 0.5mm, TI Recommended)
pins: 1 GND (power) "Ground", 2 A (in) "LVDS input, positive", 3 B (in) "LVDS input, negative", 4 NC "No connect", 5 VCC (power) "Core supply voltage", 6 NC "No connect", 7 GND (power), 8 R (out) "1.8/2.5 LVCMOS/3.3 LVTTL output", 9 NC "No connect", 10 VDD (power) "Output drive voltage"

## SN74AHC1G04DBVR
designator U?
SINGLE SCHMITT-TRIGGER INVERTER GATE, DBV0005A; Alternate PartNumber: SN74AHC1G04DBVT; Manufacturer: Texas Instruments; SymbolCreator: a0411947; CompType: IC; U/M: EA
footprint DBV0005A_N
footprint DBV0005A_M
footprint DBV0005A_L
pins: 1 NC, 2 A (in), 3 GND (power), 4 Y (out), 5 VCC (power)
2 alternate drawings of the same symbol

## SN74AUP1G80DCK
designator U?
IC, Single Positive-Edge-Triggered D-Type Flip-Flop; Manufacturer: TI; Alternate Manufacturer: None; Area: 23200
footprint DCK-5
pins: 1 D, 2 CLK, 3 GND, 4 ~Q, 5 VCC

## SN74AUP1T34DCKR
designator U?  (value not drawn)
1-Bit Unidirectional Voltage-Level Translator, DCK0005A; Manufacturer: Texas Instruments; SymbolCreator: x0208325; CompType: IC; U/M: EA
footprint DCK0005A_N
footprint DCK0005A_M
footprint DCK0005A_L
pins: 1 VCCA (power), 2 GND (power), 3 A (in), 4 B (out), 5 VCCB (power)

## SN6501DBVR
designator U?
Transformer Driver for Isolated Power Supplies, DBV0005A; Alternate PartNumber: SN6501DBVT; Manufacturer: Texas Instruments; SymbolCreator: a0411947; CompType: IC; U/M: EA
footprint DBV0005A_N
footprint DBV0005A_M
footprint DBV0005A_L
pins: 1 D1 (out), 2 VCC (power), 3 D2 (out), 4 GND (power), 5 GND (power)
1 alternate drawing of the same symbol

## THS4551IRGTR
designator U?
Low Power, Precision, 160MHz, Fully Differential Amplifier, RGT0016A; Alternate PartNumber: THS4551IRGTT; Manufacturer: Texas Instruments; SymbolCreator: Altium; SizeX_mm: 4; SizeZ_mm: 1; CompType: IC; U/M: EA
footprint RGT0016A
footprint RGT0016A_NV
pins: 1 FB- (out) "Inverted (negative) output feedback", 2 IN+ (in) "Noninverting (positive) amplifier input", 3 IN- (in) "Inverting (negative) amplifier input", 4 FB+ (out) "Noninverted (positive) output feedback", 5 VS+ (power) "Positive power-supply input", 6 VS+ (power) "Positive power-supply input", 7 VS+ (power) "Positive power-supply input", 8 VS+ (power) "Positive power-supply input", 9 VOCM (in) "Common-mode voltage input", 10 OUT+ (out) "Noninverted (positive) amplifier output", 11 OUT- (out) "Inverted (negative) amplifier output", 12 ~{PD} (in) "Power down. PD = logic low = power off mode; PD = logic high = normal operation.", 13 VS- (power) "Negative power-supply input", 14 VS- (power) "Negative power-supply input", 15 VS- (power) "Negative power-supply input", 16 VS- (power) "Negative power-supply input", 17 EP (power)
1 alternate drawing of the same symbol

## TI_Logo
designator Logo?, comment Texas Instruments  (no BOM)
Texas Instrument Corporate Signature; SymbolCreator: codlsc
footprint TI_Stacked_SolderMask_Medium
footprint TI_Stacked_SolderMask_Small
footprint TI_Stacked_Overlay_Medium
footprint TI_Stacked_Overlay_Small
footprint TI_Horizontal_SolderMask_Medium
footprint TI_Horizontal_SolderMask_Small
footprint TI_Horizontal_Overlay_Medium
footprint TI_Horizontal_Overlay_Small
footprint TI_Symbol_SolderMask_Small
footprint TI_Symbol_Overlay_Medium
footprint TI_Symbol_Overlay_Small
footprint TI_Symbol_SolderMask_Medium

## TP1_PD40_D0.5_S50
designator TP?  (value not drawn)
Test Point 40mil pad 20mil drill; Manufacturer: STD; Value: STD
footprint TP-040_RND
pins: 1

## TP-025-SMT
designator TP?  (value not drawn)
Test Point, O.025"; Manufacturer: STD; Value: STD
footprint TP_25MIL-SMT
pins: 1

## TPS7A4700RGWR
designator U?
36-V, 1-A, 4.17-μVRMS, RF LDO Voltage Regulator, RGW0020A; Alternate PartNumber: TPS7A4700RGWT; Manufacturer: Texas Instruments; SymbolCreator: a0412235; CompType: IC; U/M: EA
footprint RGW0020A
pins: 1 OUT (power), 2 NC, 3 SENSE (in), 4 6P4V2, 5 6P4V1, 6 3P2V, 7 GND (power), 8 1P6V, 9 0P8V, 10 0P4V, 11 0P2V, 12 0P1V, 13 EN (in), 14 NR (in), 15 IN (power), 16 IN (power), 17 NC, 18 NC, 19 NC, 20 OUT (power), 21 PAD

## TPS70933DBVT
designator U?, comment TPS70918DBVT
IC REG LDO 1.8V 0.15A SOT23-5; Alternate Manufacturer: None; Manufacturer: Texas Instruments; SymbolCreator: a0411947; U/M: EA
footprint DBV0005A_N
footprint DBV0005A_M
footprint DBV0005A_L
pins: 1 IN (power), 2 GND (power), 3 EN (in), 4 NC, 5 OUT (power)
1 alternate drawing of the same symbol

## TS5A3159ADCKR
designator U?
1-Ohm SPDT ANALOG SWITCH 5-V/3.3-V SINGLE-CHANNEL 2:1 MULTIPLEXER/DEMULTIPLEXER, DCK0006A; Alternate PartNumber: TS5A3159ADCKT; Manufacturer: Texas Instruments; SymbolCreator: a0799628; CompType: IC; U/M: EA
footprint DCK0006A_N
footprint DCK0006A_M
footprint DCK0006A_L
pins: 1 NO (io), 2 GND (power), 3 NC (io), 4 COM (io), 5 V+ (power), 6 IN (in)
1 alternate drawing of the same symbol

## UMK325AB7106KM-T
designator C?  ValueDisplayed: 10µF  (hidden comment: UMK325AB7106KM-T)
CAP, CERM, 10 µF, 50 V, +/- 10%, X7R, 1210; Manufacturer: Taiyo Yuden; Polarized: N; CompType: Capacitor; Value: 10uF; U/M: EA; Cap_F: 0.00001; Tolerance_%: 10; Value1: Unknown; VDC_V: 50; Value2: 50V; TaMin_C: -55; TaMax_C: 125; Cap_Case: 1210; AEC Category: Q200
signal-integrity model Cap
simulation model Cap
footprint 1210_280
pins: 1, 2

## WSL0805R0100FEA18
designator R?  ValueDisplayed: 0.01  (hidden comment: WSL0805R0100FEA18)
RES, 0.01, 1%, 0.25 W, 0805; Manufacturer: Vishay-Dale; CompType: Resistor; Value: 0.01; Value_Code: R010; Tolerance_%: 1; Power_W: 0.25; Value2: 0.25W; TempCo: 75 ppm/C; EIA_Code: E96; U/M: EA; AEC Category: Q200
signal-integrity model Resistor
simulation model Resistor
footprint 0805_HV
footprint 0805_HV1
footprint 0805
footprint 0805M
pins: 1, 2

## ZRB18AD71A106KE01L
designator C?  ValueDisplayed: 10µF  (hidden comment: ZRB18AD71A106KE01L)
CAP, CERM, 10 µF, 10 V, +/- 10%, X7T, 0603; Manufacturer: MuRata; Polarized: N; CompType: Capacitor; Value: 10uF; U/M: EA; Cap_F: 0.00001; Tolerance_%: 10; Value1: Unknown; Value2: 10V; TaMin_C: -55; TaMax_C: 125; Cap_Case: 0603; AEC Category: Q200
signal-integrity model Cap
simulation model Cap
footprint 0603_120
pins: 1, 2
